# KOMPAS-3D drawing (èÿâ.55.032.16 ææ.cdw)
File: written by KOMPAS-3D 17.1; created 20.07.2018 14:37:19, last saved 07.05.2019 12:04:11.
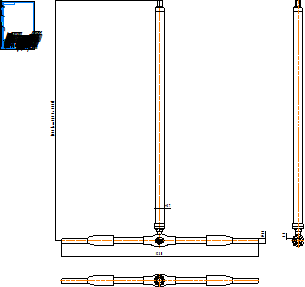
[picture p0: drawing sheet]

Sheet 1: A4, portrait

Title block, sheet 1: name: КШГ.55.032.16 СС; material: Внимание! Данный продукт является объектом авторского права ООО «Торговый Дом АДЛ». / Запрещается изменение, копирование, распространение / (в том числе путем копирования на другие сайты и ресурсы в Интернете) / или любое иное использование информации и объектов без предварительного / согласия правообладателя (ООО «Торговый Дом АДЛ»).; sheets: 1; organisation: ООО "Торговый дом АДЛ"; sheet format: A4; stored path: C:\Users\tra\Desktop\2д чертежи\Шаровые краны БИВАЛ\КШ_Бивал_серия_44_45_55\KOMPAS 2D\КШГ.55.032.16 СС.cdw

Views: Вид 1, Проекционный вид 2, Проекционный вид 3
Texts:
  kka
  adl
  (от 245 до 5000)
Dimensions and other numbers on the sheet: 1230; 1500; 57; 32; 3,5; 1:1; 1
